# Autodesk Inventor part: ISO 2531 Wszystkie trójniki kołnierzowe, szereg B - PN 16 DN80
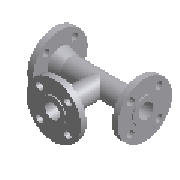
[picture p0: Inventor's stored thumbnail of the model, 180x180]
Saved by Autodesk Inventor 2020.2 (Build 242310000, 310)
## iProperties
Manager: www.cadconsulting.pl
Company: Fabian Stasiak CAD Consulting
IsCustomPart: 0
NAME: PIPING: ISO 2531 All Flanged Tee Series B - PN 16
DATA: <meta><inlinegroups number="1" deflen="25.5"></inlinegroups><connections number="3"></connections><angles><a>3.14159265358979</a><a>1.57079632679489</a></angles
Created: 2014-02
Part Number: ISO 2531 Wszystkie trójniki kołnierzowe, szereg B - PN 16 DN80
Material: Żeliwo sferoidalne
Description: Rury, łączniki, akcesoria z żeliwa sferoidalnego i ich złącza do zastosowań w instalacjach wodnych lub gazowych - Wszystkie trójniki kołnierzowe, szereg B - PN
Document SubType Name: Modeling
Standard: ISO 2531
Designer: F.Stasiak
Standard Revision: Fifth edition 1998-08-15
Standards Organization: ISO
Language: pl-PL
Size Designation: DN80
Categories: <MemberInstance><Categories><Category DisplayName="Rury cienko- i grubościenne" InternalName="4347fa0f-2144-441d-94cd-e3e15c92b736" Mnemonic="TUBEANDPIPE"><Cate
Density: 7.15 g/cm^3
Appearance: Ciemnoszary
Catalog Web Link: www.expertbooks.pl
Author: F.Stasiak
Subject: Zbiór ćwiczeń. Autodesk Inventor 2020. Kurs Professional
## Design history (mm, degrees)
sketch "Sketch1"
  geometry: L1 (0, 40)-(330, 40); L2 (330, 40)-(330, 0); L3 (330, 0)-(0, 0); L4 (0, 0)-(0, 40); L5 (0, 40)-(0, 60); L6 (0, 60)-(3, 60); L7 (3, 60)-(3, 100); L8 (3, 100)-(19, 100); L9 (19, 100)-(19, 60); L10 (67.517, 47)-(262.483, 47); L11 (165, 0)-(165, 47); L12 (311, 100)-(311, 60); L13 (327, 100)-(311, 100); L14 (327, 60)-(327, 100); L15 (330, 60)-(327, 60); L16 (330, 40)-(330, 60); L17 (19, 60)-(67.517, 47); L18 (19, 60)-(1.5, 60); L19 (311, 60)-(262.483, 47); L20 (19, 60)-(311, 60); 1 further point
  constraints: 40 end point, 6 parallel, 4 symmetric about line, 3 midpoint, 3 perpendicular, 2 collinear, 2 horizontal, 1 coincident, 5 other
  dimensions: "d0" = 80 diameter of L1 L3 (= ID); "d1" = 7 distance between parallel lines of L1 L10 (= e1); "d2" = 120 diameter of L6 L3 (= N3); "d3" = 200 diameter of L8 L3 (= D); "d4" = 3 distance of L5.end L6.end; "d5" = 19 distance between parallel lines of L9 L5 (= C7); "d6" = 165 distance between parallel lines of L2 L11 (= 0.5 x L); "d24" = 15 deg angle of L10 L17; "d25" = 15 deg angle of L10 L19
revolve "Revolution1" sketch "Sketch1" stored, may be unused: angle "d7" = 90 deg
workplane "Work Plane1"
sketch "Sketch2"
  geometry: L1 (330, 0)-(0, 0) reference; L2 (165, 0)-(165, 47) reference; C1 r 47 at (165, 0); C2 r 40 at (165, 0)
  constraints: 2 centre point, 2 coincident, 1 concentric
  dimensions: "d9" = 80 diameter of C2 (= ID2); "d10" = 94 diameter of C1 (= ID2 + 2 x e2)
extrude "Extrusion1" join sketch "Sketch2" stored distance "d11" = 25.4; taper "d12" = 0 deg
extrude "Extrusion2" cut sketch "Sketch2" stored distance "d13" = 25.4; taper "d14" = 0 deg
sketch "Sketch3"
  geometry: L1 (-125, 146)-(-65, 146); L2 (-65, 146)-(-65, 162); L3 (-65, 162)-(-105, 162); L4 (-105, 162)-(-105, 165); L5 (-105, 165)-(-125, 165); L6 (-125, 165)-(-125, 146); L7 (-125, 146)-(-165, 146); L8 (-165, 146)-(-165, 165); L9 (-165, 165)-(-125, 165); L10 (-205, 165)-(-125, 165) reference; 1 further point
  constraints: 18 end point, 5 parallel, 3 perpendicular, 1 coincident, 1 horizontal
  dimensions: "d15" = 120 diameter of L4 L8 (= N32); "d16" = 3 distance between parallel lines of L3 L5; "d17" = 19 distance between parallel lines of L1 L5 (= C72); "d18" = 200 diameter of L2 L8 (= D2)
revolve "Revolution2" sketch "Sketch3" stored, may be unused: angle "d20" = 90 deg
sketch "Sketch7"
  geometry: L1 (30.615, 73.91)-(0, 0); L2 (0, 0)-(0, 80); C1 r 60 at (0, 0) reference; C2 r 9.5 at (30.615, 73.91); A1 r 80 centre (0, 0) between (30.615, 73.91) and (0, 80)
  constraints: 4 end point, 2 centre point, 2 point on circle, 1 coincident, 1 vertical
  dimensions: "d36" = 22.5 deg angle of L1 L2 (computed from NU); "d37" = 19 diameter of C2 (= L2); "d39" = 160 diameter of A1 (= K1)
extrude "Extrusion4" cut sketch "Sketch7" taper "d40" = 0 deg; stored distance "d46" = 10
pattern_circular "Circular Pattern1" dims angle "d21" = 360 deg
sketch "Sketch5"
  geometry: L1 (-265, 146)-(-65, 146) reference; L2 (-212, 146)-(-212, 47) reference; L3 (-118, 146)-(-118, 47) reference; L4 (-212, 146)-(-225, 146); L5 (-225, 146)-(-212, 97.483); L6 (-212, 97.483)-(-212, 146); L7 (-165, 146)-(-165, 47); L8 (-212, 47)-(-118, 47); L9 (-118, 146)-(-105, 146); L10 (-105, 146)-(-118, 97.483); L11 (-118, 97.483)-(-118, 146)
  constraints: 16 end point, 3 perpendicular, 3 symmetric about line, 2 collinear, 2 midpoint, 1 parallel, 3 other
  dimensions: "d27" = 120 diameter of L4.end L7 (= N32); "d28" = 15 deg angle of L2 L5
revolve "Revolution4" sketch "Sketch5" stored, may be unused: angle "d35" = 90 deg
sketch "Sketch6"
  geometry: L1 (73.91, -30.615)-(-73.91, 30.615); L2 (0, 0)-(80, 0); C1 r 100 at (0, 0) reference; C2 r 60 at (0, 0) reference; C3 r 9.5 at (73.91, -30.615); A1 r 80 centre (0, 0) between (73.91, -30.615) and (-73.91, 30.615)
  constraints: 4 end point, 3 point on circle, 2 centre point, 2 coincident, 1 concentric, 1 horizontal, 1 midpoint
  dimensions: "d30" = 160 diameter of A1 (= K12); "d31" = 19 diameter of C3 (= L22); "d42" = 22.5 deg angle of L2 L1 (computed from NU2)
extrude "Extrusion3" cut sketch "Sketch6" taper "d32" = 0 deg; stored distance "d38" = 10
pattern_circular "Circular Pattern3" dims angle "d34" = 360 deg
sketch "Sketch8"
  geometry: L1 (0, 0)-(0, 80); L2 (0, 0)-(30.615, 73.91); C1 r 60 at (0, 0) reference; C2 r 9.5 at (30.615, 73.91); A1 r 80 centre (0, 0) between (0, 80) and (30.615, 73.91); 1 further point
  constraints: 4 end point, 2 centre point, 2 coincident, 2 point on circle, 1 vertical
  dimensions: "d49" = 22.5 deg angle of L2 L1 (computed from NU); "d50" = 19 diameter of C2 (= L2); "d51" = 160 diameter of A1 (= K1)
extrude "Extrusion5" cut sketch "Sketch8" stored distance "d52" = 10; taper "d53" = 0 deg
pattern_circular "Circular Pattern4" dims angle "d55" = 360 deg
workaxis "Work Axis2"
workpoint "Work Point1"
workaxis "Work Axis3"
workpoint "Work Point2"
workaxis "Work Axis4"
workpoint "Work Point3"
body "Solid1"
other parameters: "D" = 200 [user parameter; used in 1 equation term], "C7" = 19 [user parameter; used in 1 equation term], "e1" = 7 [user parameter; used in 1 equation term], "ID" = 80 [user parameter; used in 1 equation term], "N3" = 120 [user parameter; used in 1 equation term], "K1" = 160 [user parameter; used in 2 equation terms], "L2" = 19 [user parameter; used in 2 equation terms], "d8" = 165 (= l1), "l1" = 165 [user parameter; used in 1 equation term], "D2" = 200 [user parameter; used in 1 equation term], "C72" = 19 [user parameter; used in 1 equation term], "ID2" = 80 [user parameter; used in 2 equation terms], "N32" = 120 [user parameter; used in 2 equation terms], "e2" = 7 [user parameter; used in 1 equation term], "K12" = 160 [user parameter; used in 1 equation term], "L22" = 19 [user parameter; used in 1 equation term], "Size_Designation" = 12.345 [user parameter]
